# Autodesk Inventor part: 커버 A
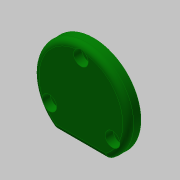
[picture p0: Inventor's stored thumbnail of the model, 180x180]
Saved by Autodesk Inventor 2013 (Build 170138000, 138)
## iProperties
Created: 2020-04
Part Number: 커버 A
Material: 알루미늄 6061
Document SubType Name: Modeling
Designer: mduedu
Density: 2.71 g/cm^3
Mass: 33.9278 g
Surface Area: 60.2978 cm^2
Volume: 12.5195 cm^3
Author: mduedu
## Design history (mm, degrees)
sketch "스케치1"
  geometry: C1 r 26 at (0, 0); 1 further point
  constraints: 1 centre point, 1 coincident
  dimensions: "d0" = 52 diameter of C1
extrude "돌출1" new body sketch "스케치1" distance "d1" = 7; taper "d2" = 0 deg
sketch "스케치2"
  geometry: L1 (-14.62, -21.5)-(14.62, -21.5); A1 r 26 centre (0, 0) between (-14.62, -21.5) and (14.62, -21.5) reference; 1 further point
  constraints: 2 end point, 2 point on circle, 1 horizontal
  dimensions: "d3" = 21.5 distance from line of L1 point (0, 0)
extrude "돌출2" cut sketch "스케치2" stored distance "d4" = 7; taper "d5" = 0 deg
fillet "모깎기1" dims "d6" = 3
fillet "모깎기2" dims "d7" = 3
sketch "스케치3" dims "d8" = 40
  geometry: 3 further points
  constraints: 2 vertical alignment, 1 coincident, 2 other
hole "구멍1" sketch "스케치3" at (0, 20) diameter "d9" = 4.5; stored, may be unused: countersink angle "d13" = 90 deg, drill point angle "d15" = 118 deg; dims "d10" = 6, "d11" = 8, "d12" = 4.4, "d14" = 8
sketch "스케치4"
  geometry: C1 r 16 at (0, 0); 1 further point
  constraints: 1 centre point, 1 coincident
  dimensions: "d19" = 32 diameter of C1
extrude "돌출3" join sketch "스케치4" distance "d20" = 3; taper "d21" = 0 deg
sketch "스케치5"
  geometry: C1 r 14 at (0, 0); 1 further point
  constraints: 1 centre point, 1 coincident
  dimensions: "d22" = 28 diameter of C1
extrude "돌출4" cut sketch "스케치5" distance "d23" = 7; taper "d24" = 0 deg
fillet "모깎기3" dims "d25" = 3
chamfer "모따기1" distance "d26" = 0.5; stored, may be unused: second distance "d27" = 2, angle "d28" = 45 deg
node "솔리드1"
pattern_circular "원형 패턴1" dims angle "d17" = 360 deg
node "투영된 루프1"
